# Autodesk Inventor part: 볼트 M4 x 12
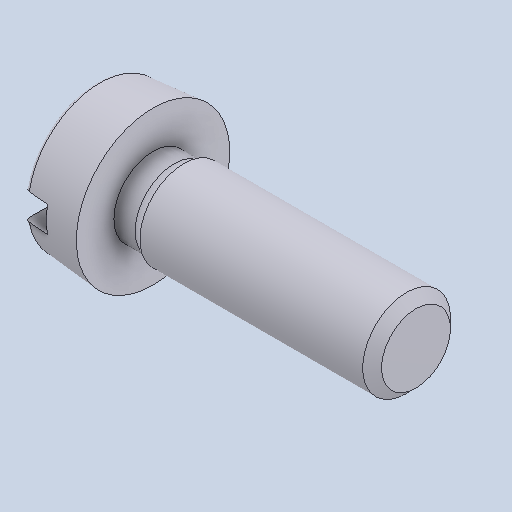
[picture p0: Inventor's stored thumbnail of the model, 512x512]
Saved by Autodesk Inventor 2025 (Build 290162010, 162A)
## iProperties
Created: 2024-07
Part Number: 볼트 M4 x 12
Material: 강철, 연강
Description: 6각머리 태핑 나사
Document SubType Name: Modeling
Designer: Admin
Density: 7.85 g/cm^3
Appearance: 기본값
Author: jhkim
Sending System: Autodesk Inventor 2025
Preprocessor: ST-DEVELOPER v20
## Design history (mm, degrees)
feature "Solid1"
node "솔리드1"
